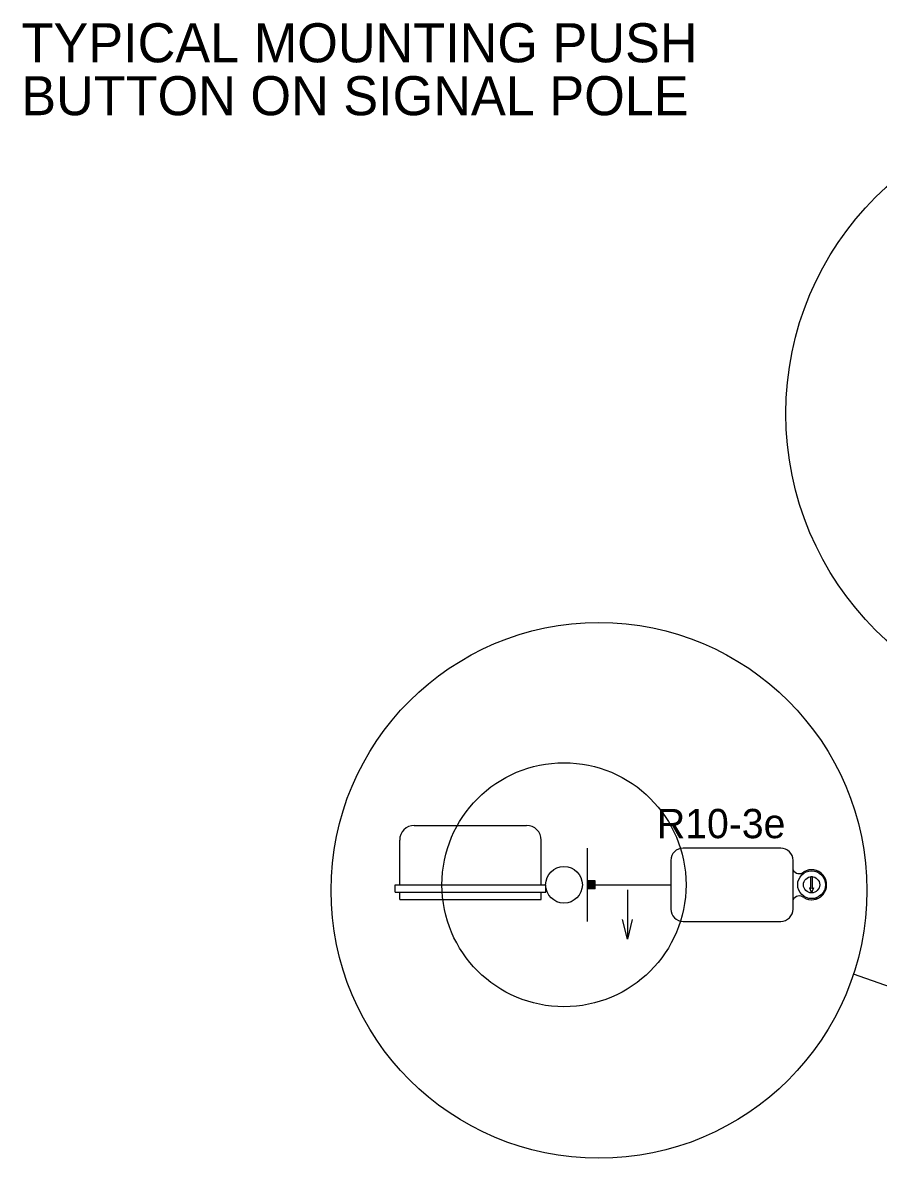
# Model space of a CAD drawing. Extents: x 1370050 to 1370716, y 380076 to 380502.
# Drawn here: x 1370535.7 to 1370623.4, y 380148.5 to 380264.8 of the extents above; entities that cross this region are included whole.
import ezdxf

# ---------------------------------------------------------------- set-up
doc = ezdxf.new("R2010")
doc.units = 0
doc.layers.add('R_Grid', color=7, linetype='Continuous')
doc.layers.add('T_Drafting', color=7, linetype='Continuous')

msp = doc.modelspace()

# ---------------------------------------------------------------- linework, layer by layer
at = {"layer": 'T_Drafting'}
for p, q in [((1370575.84, 380182.6), (1370587.34, 380182.6)), ((1370574.34, 380176.52), (1370574.34, 380181.1)), ((1370588.84, 380176.52), (1370588.84, 380181.1)), ((1370593.55, 380180.27), (1370593.55, 380172.77)), ((1370613.38, 380180.27), (1370603.37, 380180.27)), ((1370602.12, 380179.02), (1370602.12, 380174.02)), ((1370614.63, 380174.02), (1370614.63, 380179.02)), ((1370594.38, 380176.93), (1370593.55, 380176.93)), ((1370593.55, 380176.1), (1370594.38, 380176.93)), ((1370593.55, 380176.12), (1370594.37, 380176.93)), ((1370593.55, 380176.13), (1370594.35, 380176.93)), ((1370593.55, 380176.15), (1370594.34, 380176.93)), ((1370593.55, 380176.16), (1370594.32, 380176.93)), ((1370593.55, 380176.18), (1370594.31, 380176.93)), ((1370593.55, 380176.19), (1370594.3, 380176.93)), ((1370593.55, 380176.2), (1370594.28, 380176.93)), ((1370593.55, 380176.22), (1370594.27, 380176.93)), ((1370593.55, 380176.23), (1370594.25, 380176.93)), ((1370593.55, 380176.25), (1370594.24, 380176.93)), ((1370593.55, 380176.26), (1370594.22, 380176.93)), ((1370593.55, 380176.27), (1370594.21, 380176.93)), ((1370593.55, 380176.29), (1370594.2, 380176.93)), ((1370593.55, 380176.3), (1370594.18, 380176.93)), ((1370593.55, 380176.32), (1370594.17, 380176.93)), ((1370593.55, 380176.33), (1370594.15, 380176.93)), ((1370593.55, 380176.34), (1370594.14, 380176.93)), ((1370593.55, 380176.36), (1370594.13, 380176.93)), ((1370593.55, 380176.37), (1370594.11, 380176.93)), ((1370593.55, 380176.39), (1370594.1, 380176.93)), ((1370593.55, 380176.4), (1370594.08, 380176.93)), ((1370593.55, 380176.42), (1370594.07, 380176.93)), ((1370593.55, 380176.43), (1370594.05, 380176.93)), ((1370593.55, 380176.44), (1370594.04, 380176.93)), ((1370593.55, 380176.46), (1370594.03, 380176.93)), ((1370593.55, 380176.47), (1370594.01, 380176.93)), ((1370593.55, 380176.49), (1370594, 380176.93)), ((1370593.55, 380176.5), (1370593.98, 380176.93)), ((1370593.55, 380176.51), (1370593.97, 380176.93)), ((1370593.55, 380176.53), (1370593.96, 380176.93)), ((1370593.55, 380176.54), (1370593.94, 380176.93)), ((1370593.55, 380176.56), (1370593.93, 380176.93)), ((1370593.55, 380176.57), (1370593.91, 380176.93)), ((1370593.55, 380176.59), (1370593.9, 380176.93)), ((1370593.55, 380176.6), (1370593.89, 380176.93)), ((1370593.55, 380176.61), (1370593.87, 380176.93)), ((1370593.55, 380176.63), (1370593.86, 380176.93)), ((1370593.55, 380176.64), (1370593.84, 380176.93)), ((1370593.55, 380176.66), (1370593.83, 380176.93)), ((1370593.55, 380176.67), (1370593.81, 380176.93)), ((1370593.55, 380176.68), (1370593.8, 380176.93)), ((1370593.55, 380176.7), (1370593.79, 380176.93)), ((1370593.55, 380176.71), (1370593.77, 380176.93)), ((1370593.55, 380176.73), (1370593.76, 380176.93)), ((1370593.55, 380176.74), (1370593.74, 380176.93)), ((1370593.55, 380176.75), (1370593.73, 380176.93)), ((1370593.55, 380176.77), (1370593.72, 380176.93)), ((1370593.55, 380176.78), (1370593.7, 380176.93)), ((1370593.55, 380176.8), (1370593.69, 380176.93)), ((1370593.55, 380176.81), (1370593.67, 380176.93)), ((1370593.55, 380176.83), (1370593.66, 380176.93)), ((1370593.55, 380176.84), (1370593.64, 380176.93)), ((1370593.55, 380176.85), (1370593.63, 380176.93)), ((1370593.55, 380176.87), (1370593.62, 380176.93)), ((1370593.55, 380176.88), (1370593.6, 380176.93)), ((1370593.55, 380176.9), (1370593.59, 380176.93)), ((1370593.55, 380176.91), (1370593.57, 380176.93)), ((1370593.55, 380176.92), (1370593.56, 380176.93)), ((1370593.56, 380176.1), (1370594.38, 380176.92)), ((1370593.58, 380176.1), (1370594.38, 380176.91)), ((1370593.59, 380176.1), (1370594.38, 380176.9)), ((1370593.6, 380176.1), (1370594.38, 380176.88)), ((1370593.62, 380176.1), (1370594.38, 380176.87)), ((1370593.63, 380176.1), (1370594.38, 380176.85)), ((1370593.65, 380176.1), (1370594.38, 380176.84)), ((1370593.66, 380176.1), (1370594.38, 380176.82)), ((1370593.67, 380176.1), (1370594.38, 380176.81)), ((1370593.69, 380176.1), (1370594.38, 380176.8)), ((1370593.7, 380176.1), (1370594.38, 380176.78)), ((1370593.72, 380176.1), (1370594.38, 380176.77)), ((1370593.73, 380176.1), (1370594.38, 380176.75)), ((1370593.74, 380176.1), (1370594.38, 380176.74)), ((1370593.76, 380176.1), (1370594.38, 380176.73)), ((1370593.77, 380176.1), (1370594.38, 380176.71)), ((1370593.79, 380176.1), (1370594.38, 380176.7)), ((1370593.8, 380176.1), (1370594.38, 380176.68)), ((1370593.82, 380176.1), (1370594.38, 380176.67)), ((1370593.83, 380176.1), (1370594.38, 380176.65)), ((1370594.38, 380176.1), (1370594.38, 380176.93)), ((1370616.46, 380177.35), (1370616.61, 380177.35)), ((1370616.46, 380176.09), (1370616.46, 380177.35)), ((1370616.61, 380176.09), (1370616.61, 380177.35)), ((1370573.88, 380176.52), (1370589.3, 380176.52)), ((1370573.88, 380175.77), (1370573.88, 380176.52)), ((1370573.88, 380175.77), (1370589.3, 380175.77)), ((1370574.34, 380175.02), (1370574.34, 380175.77)), ((1370588.84, 380175.02), (1370588.84, 380175.77)), ((1370589.3, 380175.77), (1370589.3, 380176.52)), ((1370594.38, 380176.1), (1370593.55, 380176.1)), ((1370593.84, 380176.1), (1370594.38, 380176.64)), ((1370593.86, 380176.1), (1370594.38, 380176.63)), ((1370593.87, 380176.1), (1370594.38, 380176.61)), ((1370593.89, 380176.1), (1370594.38, 380176.6)), ((1370593.9, 380176.1), (1370594.38, 380176.58)), ((1370593.91, 380176.1), (1370594.38, 380176.57)), ((1370593.93, 380176.1), (1370594.38, 380176.56)), ((1370593.94, 380176.1), (1370594.38, 380176.54)), ((1370593.96, 380176.1), (1370594.38, 380176.53)), ((1370593.97, 380176.1), (1370594.38, 380176.51)), ((1370593.99, 380176.1), (1370594.38, 380176.5)), ((1370594, 380176.1), (1370594.38, 380176.49)), ((1370594.01, 380176.1), (1370594.38, 380176.47)), ((1370594.03, 380176.1), (1370594.38, 380176.46)), ((1370594.04, 380176.1), (1370594.38, 380176.44)), ((1370594.06, 380176.1), (1370594.38, 380176.43)), ((1370594.07, 380176.1), (1370594.38, 380176.41)), ((1370594.08, 380176.1), (1370594.38, 380176.4)), ((1370594.1, 380176.1), (1370594.38, 380176.39)), ((1370594.11, 380176.1), (1370594.38, 380176.37)), ((1370594.13, 380176.1), (1370594.38, 380176.36)), ((1370594.14, 380176.1), (1370594.38, 380176.34)), ((1370594.15, 380176.1), (1370594.38, 380176.33)), ((1370594.17, 380176.1), (1370594.38, 380176.32)), ((1370594.18, 380176.1), (1370594.38, 380176.3)), ((1370594.2, 380176.1), (1370594.38, 380176.29)), ((1370594.21, 380176.1), (1370594.38, 380176.27)), ((1370594.23, 380176.1), (1370594.38, 380176.26)), ((1370594.24, 380176.1), (1370594.38, 380176.24)), ((1370594.25, 380176.1), (1370594.38, 380176.23)), ((1370594.27, 380176.1), (1370594.38, 380176.22)), ((1370594.28, 380176.1), (1370594.38, 380176.2)), ((1370594.3, 380176.1), (1370594.38, 380176.19)), ((1370594.31, 380176.1), (1370594.38, 380176.17)), ((1370594.32, 380176.1), (1370594.38, 380176.16)), ((1370594.34, 380176.1), (1370594.38, 380176.15)), ((1370594.35, 380176.1), (1370594.38, 380176.13)), ((1370594.37, 380176.1), (1370594.38, 380176.12)), ((1370594.38, 380176.52), (1370602.12, 380176.52)), ((1370594.38, 380176.1), (1370594.38, 380176.1)), ((1370597.66, 380175.99), (1370597.66, 380170.95)), ((1370616.33, 380176.19), (1370616.53, 380175.68)), ((1370616.46, 380176.09), (1370616.33, 380176.19)), ((1370616.73, 380176.19), (1370616.53, 380175.68)), ((1370616.73, 380176.19), (1370616.61, 380176.09)), ((1370574.34, 380175.02), (1370588.84, 380175.02)), ((1370603.37, 380172.77), (1370613.38, 380172.77)), ((1370634.79, 380162.39), (1370620.82, 380167.37))]:
    msp.add_line(p, q, dxfattribs=at)
msp.add_lwpolyline([(1370598.16, 380172.95), (1370597.66, 380170.95), (1370597.16, 380172.95)], dxfattribs=at)
for centre, radius in [((1370645.25, 380224.78), 31.35), ((1370594.75, 380175.94), 27.44), ((1370591.17, 380176.52), 12.5), ((1370591.17, 380176.52), 1.88), ((1370616.53, 380176.52), 1.42), ((1370616.53, 380176.52), 0.833)]:
    msp.add_circle(centre, radius, dxfattribs=at)
for centre, radius, start, end in [((1370575.84, 380181.1), 1.5, 90, 180), ((1370587.34, 380181.1), 1.5, 360, 90), ((1370603.37, 380179.02), 1.25, 90, 180), ((1370613.38, 380179.02), 1.25, 0, 90), ((1370615.27, 380178.36), 0.7, 205.1956, 311.8028), ((1370616.53, 380176.52), 1.54, 238.7402, 121.2598), ((1370616.53, 380176.52), 1.54, 42.5066, 121.2598), ((1370615.27, 380174.68), 0.7, 48.1972, 154.8044), ((1370616.53, 380176.52), 1.54, 238.7402, 317.4934), ((1370603.37, 380174.02), 1.25, 180, 270), ((1370613.38, 380174.02), 1.25, 270, 0)]:
    msp.add_arc(centre, radius, start, end, dxfattribs=at)

# ---------------------------------------------------------------- texts
at = {"layer": 'R_Grid'}
for s, p in [('TYPICAL MOUNTING PUSH ', (1370535.61, 380260.77)), ('BUTTON ON SIGNAL POLE ', (1370535.58, 380255.35))]:
    msp.add_text(s, height=4, dxfattribs=at).set_placement(p)
at = {"layer": 'T_Drafting'}
msp.add_text('R10-3e', height=3, dxfattribs=at).set_placement((1370600.69, 380181.29))

doc.saveas('drawing.dxf')
